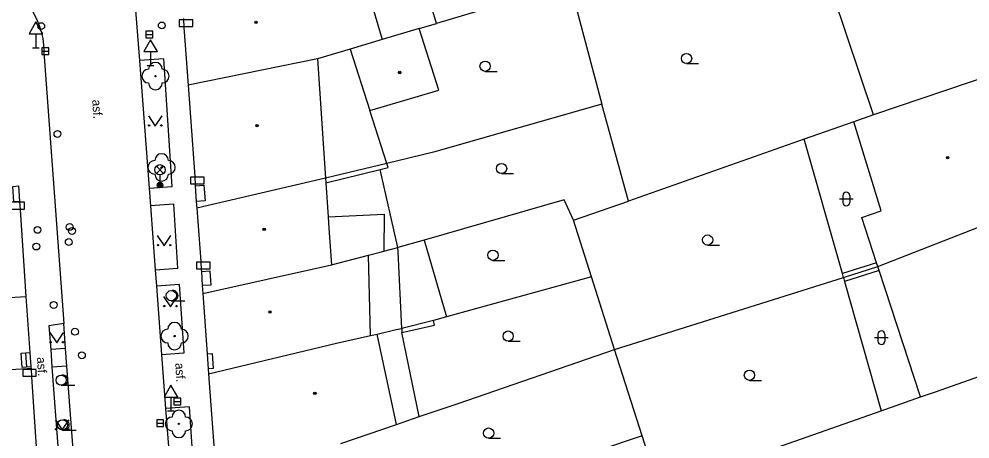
# Model space of a CAD drawing. Extents: x -596229 to -595156, y -1161237 to -1159376.
# Drawn here: x -596080.4 to -596010.8, y -1161130.8 to -1161100 of the extents above; entities that cross this region are included whole.
import ezdxf

# ---------------------------------------------------------------- set-up
doc = ezdxf.new("R2010")
doc.units = 0
for name, color, linetype in [('DOP - kresba z DSPS bez souradnic', 7, 'Continuous'), ('DOP - rozhrani ploch obecne', 7, 'Continuous'), ('Level 22', 7, 'Continuous'), ('Level 24', 7, 'Continuous'), ('Level 26', 7, 'Continuous'), ('Level 27', 7, 'Continuous'), ('Level 28', 7, 'Continuous'), ('Level 31', 7, 'Continuous'), ('Level 33', 7, 'Continuous'), ('Level 34', 7, 'Continuous'), ('Level 36', 7, 'Continuous'), ('Level 39', 7, 'Continuous'), ('TM - budovy zdene_ betonove - NP', 7, 'Continuous'), ('TM - budovy zdene_ betonove - VP', 7, 'Continuous'), ('TM - chodniky - VP', 7, 'Continuous'), ('TM - komunikace - VP', 7, 'Continuous'), ('TM - letecke snimky - pomocna linie', 7, 'Continuous'), ('TM - popis povrchu', 7, 'Continuous'), ('TM - rozhrani mezi zpev. plochami mezi sebou - VP', 7, 'Continuous'), ('TM - rozhrani ploch obecne - VP', 7, 'Continuous'), ('TM - schody - NP', 7, 'Continuous')]:
    doc.layers.add(name, color=color, linetype=linetype)

msp = doc.modelspace()

# ---------------------------------------------------------------- linework, layer by layer
at = {"layer": 'DOP - kresba z DSPS bez souradnic'}
for points in [[(-596057.98, -1161112.03), (-596053.99, -1161111.05)], [(-596017.63, -1161117.89), (-596020.14, -1161118.68)], [(-596017.44, -1161118.46), (-596019.98, -1161119.26)], [(-596050.01, -1161122.46), (-596050.09, -1161122.11)], [(-596052.4, -1161123), (-596050.01, -1161122.46)]]:
    msp.add_lwpolyline(points, dxfattribs=at)
at = {"layer": 'DOP - rozhrani ploch obecne'}
for points in [[(-596040.11, -1161097.42), (-596049.86, -1161100.35)], [(-596040.11, -1161097.42), (-596037.75, -1161106.28)], [(-596037.75, -1161106.28), (-596050.09, -1161109.78)], [(-596035.81, -1161113.38), (-596037.75, -1161106.28)], [(-596053.5, -1161110.62), (-596054.74, -1161106.74)], [(-596019.31, -1161107.56), (-596022.94, -1161108.84)], [(-596022.94, -1161108.84), (-596035.81, -1161113.38)], [(-596020.14, -1161118.68), (-596022.94, -1161108.84)], [(-596050.09, -1161109.78), (-596053.5, -1161110.62)], [(-596053.5, -1161110.62), (-596058, -1161111.68)], [(-596053.99, -1161111.05), (-596053.41, -1161110.91)], [(-596052.7, -1161116.78), (-596053.99, -1161111.05)], [(-596053.41, -1161110.91), (-596053.5, -1161110.62)], [(-596040.52, -1161113.29), (-596050.78, -1161116.23)], [(-596039.84, -1161114.76), (-596040.52, -1161113.29)], [(-596039.84, -1161114.76), (-596035.81, -1161113.38)], [(-596038.52, -1161118.92), (-596039.84, -1161114.76)], [(-596050.78, -1161116.23), (-596052.7, -1161116.78)], [(-596057.56, -1161118.04), (-596054.86, -1161117.34)], [(-596054.86, -1161117.34), (-596054, -1161117.12)], [(-596054, -1161117.12), (-596053.72, -1161117.05)], [(-596053.72, -1161117.05), (-596052.7, -1161116.78)], [(-596052.68, -1161117.09), (-596052.7, -1161116.78)], [(-596052.41, -1161122.7), (-596052.68, -1161117.09)], [(-596020.06, -1161118.97), (-596020.14, -1161118.68)], [(-596020.06, -1161118.97), (-596017.54, -1161118.17)], [(-596038.52, -1161118.92), (-596049.14, -1161121.85)], [(-596036.82, -1161124.25), (-596038.52, -1161118.92)], [(-596036.82, -1161124.25), (-596020.06, -1161118.97)], [(-596020.06, -1161118.97), (-596019.98, -1161119.26)], [(-596019.98, -1161119.26), (-596017.29, -1161128.73)], [(-596050.09, -1161122.11), (-596052.41, -1161122.7)], [(-596049.14, -1161121.85), (-596050.09, -1161122.11)], [(-596054.21, -1161123.11), (-596052.81, -1161122.79), (-596052.41, -1161122.7)], [(-596052.41, -1161122.7), (-596052.4, -1161123)], [(-596057.18, -1161123.79), (-596054.69, -1161123.22)], [(-596054.69, -1161123.22), (-596054.21, -1161123.11)], [(-596051.13, -1161129.16), (-596048.29, -1161128.19), (-596036.82, -1161124.25)], [(-596034.8, -1161130.57), (-596036.82, -1161124.25)], [(-596017.29, -1161128.73), (-596014.41, -1161127.72)], [(-596033.56, -1161134.46), (-596017.29, -1161128.73)], [(-596034.8, -1161130.57), (-596044.68, -1161133.89)], [(-596033.56, -1161134.46), (-596034.8, -1161130.57)]]:
    msp.add_lwpolyline(points, dxfattribs=at)
at = {"layer": 'Level 22'}
for centre in [(-596070.45, -1161104.21), (-596070, -1161110.9), (-596069.05, -1161123.26), (-596068.74, -1161129.7)]:
    msp.add_circle(centre, 0.05, dxfattribs=at)
for centre, start, end in [((-596070.45, -1161103.71), 0, 180), ((-596070.95, -1161104.21), 90, 270), ((-596069.95, -1161104.21), 270, 90), ((-596070.45, -1161104.71), 180, 0), ((-596070.5, -1161110.9), 90, 270), ((-596070, -1161110.4), 0, 180), ((-596069.5, -1161110.9), 270, 90), ((-596070, -1161111.4), 180, 0), ((-596069.05, -1161122.76), 0, 180), ((-596069.55, -1161123.26), 90, 270), ((-596068.55, -1161123.26), 270, 90), ((-596069.05, -1161123.76), 180, 0), ((-596069.24, -1161129.7), 90, 270), ((-596068.74, -1161129.2), 0, 180), ((-596068.24, -1161129.7), 270, 90), ((-596068.74, -1161130.2), 180, 0)]:
    msp.add_arc(centre, 0.5, start, end, dxfattribs=at)
at = {"layer": 'Level 24'}
for points in [[(-596068.707, -1161100.578), (-596067.707, -1161100.578), (-596067.707, -1161100.078), (-596068.707, -1161100.078)], [(-596067.877, -1161112.108), (-596066.877, -1161112.108), (-596066.877, -1161111.608), (-596067.877, -1161111.608)], [(-596081.047, -1161113.958), (-596080.047, -1161113.958), (-596080.047, -1161113.458), (-596081.047, -1161113.458)], [(-596067.447, -1161118.338), (-596066.447, -1161118.338), (-596066.447, -1161117.838), (-596067.447, -1161117.838)], [(-596080.177, -1161126.208), (-596079.177, -1161126.208), (-596079.177, -1161125.708), (-596080.177, -1161125.708)]]:
    msp.add_lwpolyline(points, close=True, dxfattribs=at)
at = {"layer": 'Level 26'}
for centre in [(-596078.82, -1161100.55), (-596069.99, -1161100.5), (-596076.56, -1161115.56), (-596076.8, -1161116.37), (-596077.91, -1161120.98)]:
    msp.add_circle(centre, 0.25, dxfattribs=at)
at = {"layer": 'Level 27'}
for p, q in [((-596071.15, -1161101.17), (-596070.65, -1161101.17)), ((-596078.77, -1161102.38), (-596078.27, -1161102.38)), ((-596069.1, -1161128.05), (-596068.6, -1161128.05)), ((-596070.36, -1161129.64), (-596069.86, -1161129.64))]:
    msp.add_line(p, q, dxfattribs=at)
for points in [[(-596071.15, -1161101.42), (-596070.65, -1161101.42), (-596070.65, -1161100.92), (-596071.15, -1161100.92)], [(-596078.77, -1161102.63), (-596078.27, -1161102.63), (-596078.27, -1161102.13), (-596078.77, -1161102.13)], [(-596069.1, -1161128.3), (-596068.6, -1161128.3), (-596068.6, -1161127.8), (-596069.1, -1161127.8)], [(-596070.36, -1161129.89), (-596069.86, -1161129.89), (-596069.86, -1161129.39), (-596070.36, -1161129.39)]]:
    msp.add_lwpolyline(points, close=True, dxfattribs=at)
at = {"layer": 'Level 28'}
for centre in [(-596077.63, -1161108.45), (-596076.73, -1161115.27), (-596079.18, -1161116.7), (-596076.35, -1161122.94), (-596075.84, -1161124.67)]:
    msp.add_circle(centre, 0.25, dxfattribs=at)
at = {"layer": 'Level 31'}
msp.add_circle((-596079.09, -1161115.48), 0.25, dxfattribs=at)
at = {"layer": 'Level 33'}
for p, q in [((-596070.385, -1161111.34), (-596069.855, -1161110.81)), ((-596070.385, -1161110.81), (-596069.855, -1161111.34)), ((-596070.12, -1161111.45), (-596070.12, -1161112.2))]:
    msp.add_line(p, q, dxfattribs=at)
for centre, radius in [((-596070.12, -1161111.075), 0.375), ((-596070.12, -1161112.2), 0.2), ((-596070.12, -1161112.2), 0.145), ((-596070.12, -1161112.2), 0.0876)]:
    msp.add_circle(centre, radius, dxfattribs=at)
at = {"layer": 'Level 34'}
for p, q in [((-596079.21, -1161101.112), (-596079.21, -1161102.13)), ((-596079.46, -1161102.13), (-596078.96, -1161102.13)), ((-596070.81, -1161102.412), (-596070.81, -1161103.43)), ((-596071.06, -1161103.43), (-596070.56, -1161103.43)), ((-596069.32, -1161127.732), (-596069.32, -1161128.75)), ((-596069.57, -1161128.75), (-596069.07, -1161128.75))]:
    msp.add_line(p, q, dxfattribs=at)
for points in [[(-596079.71, -1161101.112), (-596078.71, -1161101.112), (-596079.21, -1161100.246)], [(-596071.31, -1161102.412), (-596070.31, -1161102.412), (-596070.81, -1161101.546)], [(-596069.82, -1161127.732), (-596068.82, -1161127.732), (-596069.32, -1161126.866)]]:
    msp.add_lwpolyline(points, close=True, dxfattribs=at)
at = {"layer": 'Level 36'}
for p, q in [((-596031.55, -1161103.295), (-596030.675, -1161103.295)), ((-596046.31, -1161103.865), (-596045.435, -1161103.865)), ((-596045.1, -1161111.355), (-596044.225, -1161111.355)), ((-596020.356, -1161113.216), (-596019.356, -1161113.216)), ((-596020.106, -1161112.966), (-596020.106, -1161113.466)), ((-596019.606, -1161112.966), (-596019.606, -1161113.466)), ((-596030.01, -1161116.595), (-596029.135, -1161116.595)), ((-596045.73, -1161117.715), (-596044.855, -1161117.715)), ((-596069.29, -1161120.675), (-596068.29, -1161120.675)), ((-596044.62, -1161123.635), (-596043.745, -1161123.635)), ((-596017.786, -1161123.376), (-596016.786, -1161123.376)), ((-596017.536, -1161123.126), (-596017.536, -1161123.626)), ((-596017.036, -1161123.126), (-596017.036, -1161123.626)), ((-596077.36, -1161126.865), (-596076.36, -1161126.865)), ((-596026.95, -1161126.505), (-596026.075, -1161126.505)), ((-596077.26, -1161130.145), (-596076.26, -1161130.145)), ((-596046.05, -1161130.745), (-596045.175, -1161130.745))]:
    msp.add_line(p, q, dxfattribs=at)
for points in [[(-596070.97, -1161107.13), (-596070.47, -1161107.88), (-596069.97, -1161107.13)], [(-596070.32, -1161115.9), (-596069.82, -1161116.65), (-596069.32, -1161115.9)], [(-596069.86, -1161120.36), (-596069.36, -1161121.11), (-596068.86, -1161120.36)], [(-596078.18, -1161123.01), (-596077.68, -1161123.76), (-596077.18, -1161123.01)], [(-596077.78, -1161129.39), (-596077.28, -1161130.14), (-596076.78, -1161129.39)]]:
    msp.add_lwpolyline(points, dxfattribs=at)
for centre, radius in [((-596031.55, -1161102.92), 0.375), ((-596046.31, -1161103.49), 0.375), ((-596070.92, -1161107.83), 0.05), ((-596070.021, -1161107.83), 0.05), ((-596045.1, -1161110.98), 0.375), ((-596030.01, -1161116.22), 0.375), ((-596070.27, -1161116.6), 0.05), ((-596069.371, -1161116.6), 0.05), ((-596045.73, -1161117.34), 0.375), ((-596069.29, -1161120.3), 0.375), ((-596069.81, -1161121.06), 0.05), ((-596068.911, -1161121.06), 0.05), ((-596044.62, -1161123.26), 0.375), ((-596078.13, -1161123.71), 0.05), ((-596077.231, -1161123.71), 0.05), ((-596026.95, -1161126.13), 0.375), ((-596077.36, -1161126.49), 0.375), ((-596077.26, -1161129.77), 0.375), ((-596077.73, -1161130.09), 0.05), ((-596076.831, -1161130.09), 0.05), ((-596046.05, -1161130.37), 0.375)]:
    msp.add_circle(centre, radius, dxfattribs=at)
for centre, radius, start, end in [((-596019.856, -1161112.966), 0.25, 0, 180), ((-596019.856, -1161113.466), 0.25, 180, 0), ((-596069.165, -1161120.3), 0.375, 260.40593, 99.59407), ((-596017.286, -1161123.126), 0.25, 0, 180), ((-596017.286, -1161123.626), 0.25, 180, 0), ((-596077.235, -1161126.49), 0.375, 260.40593, 99.59407), ((-596077.135, -1161129.77), 0.375, 260.40593, 99.59407)]:
    msp.add_arc(centre, radius, start, end, dxfattribs=at)
at = {"layer": 'Level 39'}
for centre, radius in [((-596063.09, -1161100.27), 0.09), ((-596063.09, -1161100.27), 0.0398), ((-596052.56, -1161103.95), 0.09), ((-596052.56, -1161103.95), 0.0398), ((-596063.01, -1161107.85), 0.09), ((-596063.01, -1161107.85), 0.0398), ((-596012.43, -1161110.19), 0.09), ((-596012.43, -1161110.19), 0.0398), ((-596062.49, -1161115.44), 0.09), ((-596062.49, -1161115.44), 0.0398), ((-596062.07, -1161121.5), 0.09), ((-596062.07, -1161121.5), 0.0398), ((-596058.78, -1161127.46), 0.09), ((-596058.78, -1161127.46), 0.0398)]:
    msp.add_circle(centre, radius, dxfattribs=at)
at = {"layer": 'TM - budovy zdene_ betonove - NP'}
for points in [[(-596080.4, -1161113.39), (-596080.82, -1161113.43), (-596080.91, -1161112.29), (-596080.48, -1161112.25)], [(-596067.54, -1161112.25), (-596066.9, -1161112.21), (-596066.82, -1161113.36), (-596067.46, -1161113.4)], [(-596067.09, -1161118.52), (-596066.47, -1161118.48), (-596066.4, -1161119.52), (-596067.02, -1161119.56)], [(-596080.22, -1161125.56), (-596080.29, -1161124.51), (-596079.65, -1161124.46)], [(-596066.66, -1161124.56), (-596066.31, -1161124.54), (-596066.22, -1161125.64), (-596066.59, -1161125.66)], [(-596079.57, -1161125.52), (-596079.89, -1161125.54), (-596080.22, -1161125.56)]]:
    msp.add_lwpolyline(points, dxfattribs=at)
at = {"layer": 'TM - budovy zdene_ betonove - VP'}
for points in [[(-596017.85, -1161107.05), (-596022.77, -1161092.41)], [(-596049.86, -1161100.35), (-596051.03, -1161096.39)], [(-596055, -1161097.62), (-596053.84, -1161101.53)], [(-596068.41, -1161099.98), (-596068.41, -1161100.04), (-596068.37, -1161100.64), (-596068.06, -1161104.87)], [(-596051.14, -1161100.73), (-596053.84, -1161101.53)], [(-596051.14, -1161100.73), (-596049.86, -1161100.35)], [(-596049.69, -1161105.24), (-596051.14, -1161100.73)], [(-596053.84, -1161101.53), (-596056.19, -1161102.23)], [(-596056.19, -1161102.23), (-596058.59, -1161102.94)], [(-596056.19, -1161102.23), (-596054.74, -1161106.74)], [(-596058.59, -1161102.94), (-596068.06, -1161104.87)], [(-596058.59, -1161102.94), (-596058, -1161111.68)], [(-596009.05, -1161104.07), (-596017.85, -1161107.05)], [(-596068.06, -1161104.87), (-596067.58, -1161111.58), (-596067.54, -1161112.17), (-596067.54, -1161112.25)], [(-596054.74, -1161106.74), (-596049.69, -1161105.24)], [(-596017.85, -1161107.05), (-596019.31, -1161107.56)], [(-596017.31, -1161114.09), (-596019.31, -1161107.56)], [(-596058, -1161111.68), (-596067.42, -1161113.9)], [(-596058, -1161111.68), (-596057.98, -1161112.03)], [(-596080.48, -1161112.25), (-596080.4, -1161113.39)], [(-596067.54, -1161112.25), (-596067.46, -1161113.4)], [(-596057.98, -1161112.03), (-596057.81, -1161114.52)], [(-596080.4, -1161113.39), (-596080.36, -1161114), (-596079.94, -1161120.36)], [(-596067.46, -1161113.4), (-596067.42, -1161113.9)], [(-596067.42, -1161113.9), (-596067.14, -1161117.8), (-596067.1, -1161118.4), (-596067.09, -1161118.52)], [(-596017.54, -1161118.17), (-596005.8, -1161113.57)], [(-596057.81, -1161114.52), (-596057.75, -1161115.35)], [(-596018.72, -1161114.57), (-596017.31, -1161114.09)], [(-596017.63, -1161117.89), (-596018.72, -1161114.57)], [(-596057.75, -1161115.35), (-596057.56, -1161118.04)], [(-596066.98, -1161120.13), (-596057.56, -1161118.04)], [(-596017.54, -1161118.17), (-596017.63, -1161117.89)], [(-596067.09, -1161118.52), (-596067.02, -1161119.56)], [(-596017.44, -1161118.46), (-596017.54, -1161118.17)], [(-596014.41, -1161127.72), (-596017.44, -1161118.46)], [(-596067.02, -1161119.56), (-596066.98, -1161120.13)], [(-596066.98, -1161120.13), (-596066.66, -1161124.56)], [(-596089.59, -1161120.95), (-596079.94, -1161120.36)], [(-596079.94, -1161120.36), (-596079.65, -1161124.46)], [(-596013.33, -1161127.34), (-596002.41, -1161123.49)], [(-596066.56, -1161126.03), (-596057.18, -1161123.79)], [(-596079.65, -1161124.46), (-596079.57, -1161125.52)], [(-596066.66, -1161124.56), (-596066.59, -1161125.66)], [(-596079.56, -1161125.65), (-596079.86, -1161125.67), (-596089.3, -1161126.23)], [(-596079.57, -1161125.52), (-596079.56, -1161125.65)], [(-596079.56, -1161125.65), (-596079.52, -1161126.25), (-596078.99, -1161134.31)], [(-596066.59, -1161125.66), (-596066.56, -1161126.03)], [(-596066.56, -1161126.03), (-596066.09, -1161132.6)], [(-596014.41, -1161127.72), (-596013.33, -1161127.34)], [(-596056.87, -1161131.13), (-596052.8, -1161129.73)]]:
    msp.add_lwpolyline(points, dxfattribs=at)
at = {"layer": 'TM - chodniky - VP'}
for points in [[(-596070.91, -1161112.43), (-596069.24, -1161112.31), (-596069.85, -1161102.94), (-596071.63, -1161103.08)], [(-596070.47, -1161118.41), (-596068.81, -1161118.29), (-596069.1, -1161113.59), (-596070.82, -1161113.72)], [(-596070, -1161124.61), (-596068.35, -1161124.49), (-596068.68, -1161119.48), (-596070.38, -1161119.61)], [(-596077.16, -1161122.35), (-596078.26, -1161122.5), (-596078.12, -1161124.25)], [(-596077.03, -1161124.18), (-596078.12, -1161124.25)], [(-596076.94, -1161125.47), (-596078.03, -1161125.54)], [(-596078.03, -1161125.54), (-596077.41, -1161133.92), (-596076.32, -1161133.84)], [(-596069.41, -1161132.6), (-596067.7, -1161132.47), (-596067.95, -1161128.45), (-596069.71, -1161128.58)]]:
    msp.add_lwpolyline(points, dxfattribs=at)
at = {"layer": 'TM - komunikace - VP'}
for points in [[(-596072.03, -1161097.85), (-596071.63, -1161103.08)], [(-596080.48, -1161098.3), (-596080.1, -1161098.63), (-596079.76, -1161099.05), (-596079.44, -1161099.51), (-596079.17, -1161100.01), (-596078.96, -1161100.5), (-596078.82, -1161100.97), (-596078.7, -1161101.45), (-596078.65, -1161101.93), (-596078.63, -1161102.47)], [(-596078.63, -1161102.47), (-596077.16, -1161122.35)], [(-596071.63, -1161103.08), (-596070.91, -1161112.43)], [(-596070.91, -1161112.43), (-596070.82, -1161113.72)], [(-596070.82, -1161113.72), (-596070.47, -1161118.41)], [(-596070.47, -1161118.41), (-596070.38, -1161119.61)], [(-596070.38, -1161119.61), (-596070, -1161124.61)], [(-596077.03, -1161124.18), (-596077.16, -1161122.35)], [(-596076.94, -1161125.47), (-596077.03, -1161124.18)], [(-596070, -1161124.61), (-596069.71, -1161128.58)], [(-596076.32, -1161133.84), (-596076.94, -1161125.47)], [(-596069.71, -1161128.58), (-596069.41, -1161132.6)]]:
    msp.add_lwpolyline(points, dxfattribs=at)
at = {"layer": 'TM - letecke snimky - pomocna linie'}
for points in [[(-596057.81, -1161114.52), (-596053.7, -1161114.33), (-596053.72, -1161117.05)], [(-596050.78, -1161116.23), (-596049.14, -1161121.85)], [(-596054.69, -1161123.22), (-596054.86, -1161117.34)], [(-596051.13, -1161129.16), (-596052.4, -1161123)], [(-596052.8, -1161129.73), (-596054.21, -1161123.11)]]:
    msp.add_lwpolyline(points, dxfattribs=at)
at = {"layer": 'TM - rozhrani mezi zpev. plochami mezi sebou - VP'}
msp.add_lwpolyline([(-596078.12, -1161124.25), (-596078.03, -1161125.54)], dxfattribs=at)
at = {"layer": 'TM - rozhrani ploch obecne - VP'}
msp.add_lwpolyline([(-596052.8, -1161129.73), (-596051.13, -1161129.16)], dxfattribs=at)
at = {"layer": 'TM - schody - NP'}
msp.add_lwpolyline([(-596079.97, -1161124.48), (-596079.89, -1161125.54)], dxfattribs=at)

# ---------------------------------------------------------------- texts
at = {"layer": 'TM - popis povrchu'}
for rotation, p in [(274.23, (-596075.09, -1161105.96)), (273.91, (-596079.14, -1161124.82)), (274.18, (-596069.01, -1161125.25))]:
    msp.add_text('asf.', height=0.65, rotation=rotation, dxfattribs=at).set_placement(p)

doc.saveas('drawing.dxf')
